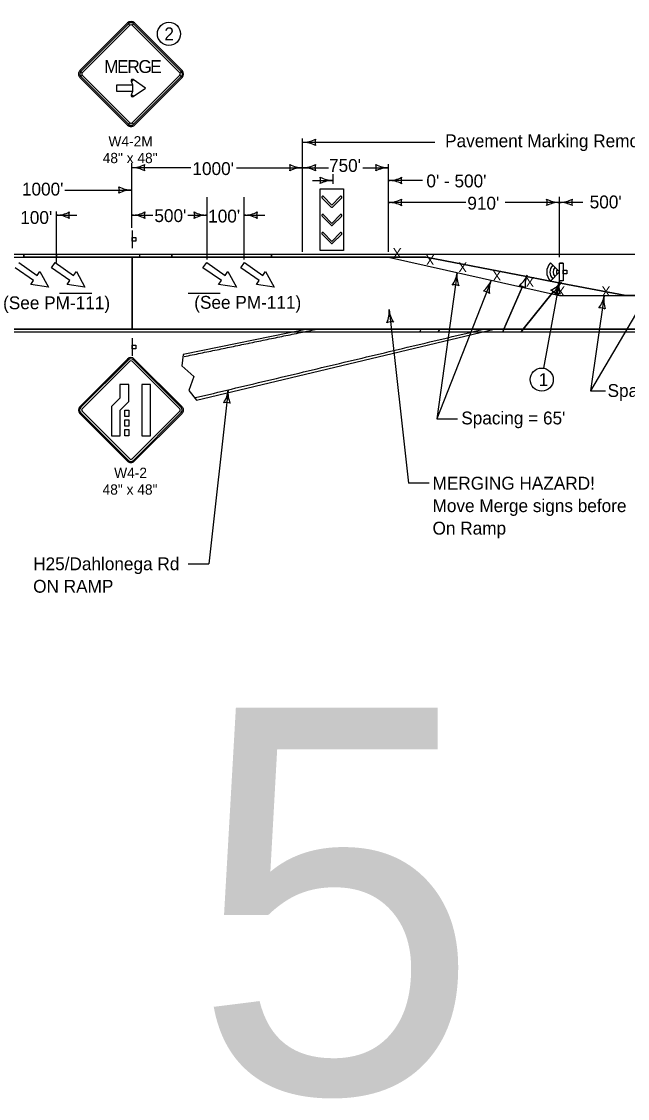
# Model space of a CAD drawing. Extents: x 10133 to 2270741, y 5363 to 1733450.
# Drawn here: x 25614 to 26557, y 10401 to 12077 of the extents above; entities that cross this region are included whole.
import ezdxf

# ---------------------------------------------------------------- set-up
doc = ezdxf.new("R2010")
doc.units = 0
for name, color, linetype in [('dsnNonPlotable', 7, 'Continuous'), ('dsnShtPlotShapeBatchPrint', 7, 'Continuous'), ('dsnStdBlockModified', 7, 'Continuous'), ('dsnStdBorder', 7, 'Continuous'), ('dsnStdNote', 7, 'Continuous'), ('Level 12', 7, 'Continuous'), ('Level 2', 7, 'Continuous'), ('SheetBorder', 7, 'Continuous'), ('SheetText', 7, 'Continuous')]:
    doc.layers.add(name, color=color, linetype=linetype)

msp = doc.modelspace()

# ---------------------------------------------------------------- linework, layer by layer
at = {"layer": 'dsnNonPlotable'}
for p, q in [((24576.8, 11710.3), (26185, 11710.3)), ((25609.6, 11702.1), (25638.2, 11682)), ((25660.4, 11693.9), (25666.1, 11702.1)), ((25666.1, 11702.1), (25694.8, 11682)), ((25896.1, 11693.9), (25901.9, 11702.1)), ((25901.9, 11702.1), (25930.5, 11682)), ((25954.9, 11693.9), (25960.6, 11702.1)), ((25960.6, 11702.1), (25989.3, 11682)), ((26185, 11710.3), (26450.8, 11650.6)), ((25632.5, 11673.8), (25603.8, 11693.9)), ((25638.2, 11682), (25642.5, 11688.1)), ((25642.5, 11688.1), (25655.8, 11663.6)), ((25689, 11673.8), (25660.4, 11693.9)), ((25694.8, 11682), (25699.1, 11688.1)), ((25699.1, 11688.1), (25712.4, 11663.6)), ((25924.8, 11673.8), (25896.1, 11693.9)), ((25930.5, 11682), (25934.8, 11688.1)), ((25934.8, 11688.1), (25948.1, 11663.6)), ((25983.6, 11673.8), (25954.9, 11693.9)), ((25989.3, 11682), (25993.6, 11688.1)), ((25993.6, 11688.1), (26006.9, 11663.6)), ((25628.2, 11667.7), (25632.5, 11673.8)), ((25684.7, 11667.7), (25689, 11673.8)), ((25920.5, 11667.7), (25924.8, 11673.8)), ((25979.3, 11667.7), (25983.6, 11673.8)), ((25655.8, 11663.6), (25628.2, 11667.7)), ((25712.4, 11663.6), (25684.7, 11667.7)), ((25948.1, 11663.6), (25920.5, 11667.7)), ((26006.9, 11663.6), (25979.3, 11667.7)), ((26450.8, 11650.6), (26599, 11650.6))]:
    msp.add_line(p, q, dxfattribs=at)
for points in [[(25673, 11654.4), (25723, 11654.4)], [(25673, 11654.4), (25723, 11654.4)], [(25873, 11654.4), (25923, 11654.4)]]:
    msp.add_lwpolyline(points, dxfattribs=at)
for points in [[(25884.3, 11491.7), (26333, 11598.3)], [(25970.2, 11577), (26073.8, 11598.3)], [(26333, 11598.3), (26597.2, 11598.3)], [(25866.6, 11555.6), (25969.4, 11576.8)]]:
    msp.add_open_spline(points, degree=1, dxfattribs=at)
at = {"layer": 'dsnShtPlotShapeBatchPrint'}
msp.add_circle((25843.2, 12058), 18, dxfattribs=at)
at = {"layer": 'dsnStdBlockModified'}
for p, q in [((26436.7, 11701.4), (26450.8, 11687.3)), ((26450.8, 11687.3), (26436.7, 11673.1)), ((26456.4, 11701), (26450.8, 11701)), ((26456.4, 11673.5), (26450.8, 11673.5))]:
    msp.add_line(p, q, dxfattribs=at)
for radius, start, end in [(20.3, 135.88, 224.0313), (15.3, 136.1665, 223.7159), (10.3, 136.7294, 223.0963), (5.32, 138.7005, 221.2995)]:
    msp.add_arc((26451.3, 11687.2), radius, start, end, dxfattribs=at)
at = {"layer": 'dsnStdBorder'}
for p, q in [((25778.9, 12075), (25704.6, 12000.7)), ((25780.2, 12073.6), (25782.4, 12071.4)), ((25786, 12071.4), (25788.2, 12073.6)), ((25863.7, 12000.7), (25789.5, 12075)), ((25704.6, 11990.1), (25778.9, 11915.9)), ((25708.2, 11997.2), (25706, 11999.4)), ((25706, 11991.4), (25708.2, 11993.6)), ((25786.2, 11985.1), (25787.3, 11986.8)), ((25789.5, 11915.9), (25863.7, 11990.1)), ((25862.4, 11999.4), (25860.2, 11997.2)), ((25860.2, 11993.6), (25862.4, 11991.4)), ((25784.3, 11984.4), (25786.2, 11985.1)), ((25786.2, 11962), (25784.3, 11962.6)), ((25787.3, 11960.3), (25786.2, 11962)), ((25782.4, 11919.4), (25780.2, 11917.2)), ((25788.2, 11917.2), (25786, 11919.4)), ((26097.8, 11788.4), (26111.9, 11802.5)), ((26097.8, 11760.1), (26111.9, 11774.2)), ((25786, 11751.8), (25786, 11724.3)), ((26097.8, 11732.1), (26111.9, 11746.2)), ((26456.4, 11701), (26456.4, 11673.5)), ((25786, 11584.3), (25786, 11556.8)), ((25778.7, 11551.8), (25704.4, 11477.6)), ((25704.5, 11477.6), (25778.7, 11551.8)), ((25778.7, 11551.8), (25778.7, 11551.8)), ((25789.3, 11551.8), (25863.6, 11477.6)), ((25863.6, 11477.6), (25789.3, 11551.8)), ((25705.8, 11476.2), (25780, 11550.5)), ((25782.2, 11548.3), (25708, 11474)), ((25782.2, 11548.3), (25782.2, 11548.3)), ((25860, 11474), (25785.8, 11548.3)), ((25788, 11550.5), (25862.2, 11476.2)), ((25780, 11394), (25705.8, 11468.3)), ((25708, 11470.5), (25782.2, 11396.2)), ((25785.8, 11396.2), (25860, 11470.5)), ((25862.2, 11468.3), (25788, 11394)), ((25704.4, 11467), (25778.7, 11392.7)), ((25778.7, 11392.7), (25704.5, 11467)), ((25863.6, 11467), (25789.3, 11392.7)), ((25789.3, 11392.7), (25863.6, 11467))]:
    msp.add_line(p, q, dxfattribs=at)
for points in [[(25780.2, 12073.6), (25706, 11999.4), (25708.2, 11997.2), (25782.4, 12071.4), (25780.2, 12073.6)], [(25862.4, 11999.4), (25788.2, 12073.6), (25786, 12071.4), (25860.2, 11997.2), (25862.4, 11999.4)], [(25706, 11991.4), (25780.2, 11917.2), (25782.4, 11919.4), (25708.2, 11993.6), (25706, 11991.4)], [(25806.5, 11973.5), (25787.3, 11986.8), (25786.2, 11985.1), (25784.3, 11984.4), (25786.3, 11978.5), (25786.3, 11968.5), (25784.3, 11962.6), (25786.2, 11962), (25787.3, 11960.3), (25806.5, 11973.5)], [(25788.2, 11917.2), (25862.4, 11991.4), (25860.2, 11993.6), (25786, 11919.4), (25788.2, 11917.2)], [(25761.9, 11968.5), (25761.9, 11978.5), (25786.3, 11978.5), (25786.3, 11968.5), (25761.9, 11968.5)], [(26114.9, 11816.5), (26114.9, 11720.5), (26078.2, 11720.5), (26078.2, 11816.5)], [(25786.1, 11735.4), (25786.1, 11741), (25791.7, 11741), (25791.7, 11735.4)], [(26450.8, 11673.5), (26450.8, 11701), (26456.4, 11701), (26456.4, 11673.5)], [(26456.4, 11684.6), (26456.4, 11690.2), (26462.1, 11690.2), (26462.1, 11684.6)], [(25786.1, 11567.9), (25786.1, 11573.5), (25791.7, 11573.5), (25791.7, 11567.9)], [(25767, 11491.1), (25753.7, 11477.9), (25753.7, 11432.3), (25767.2, 11432.3), (25767.2, 11472.3), (25780.5, 11485.5), (25780.5, 11512.3), (25767, 11512.3)], [(25800.8, 11512.3), (25800.8, 11432.3), (25814.3, 11432.3), (25814.3, 11512.3)], [(25774.5, 11472.3), (25780.5, 11472.3), (25780.5, 11462.3), (25774.5, 11462.3)], [(25774.5, 11457.3), (25780.5, 11457.3), (25780.5, 11447.3), (25774.5, 11447.3)], [(25774.5, 11442.3), (25780.5, 11442.3), (25780.5, 11432.3), (25774.5, 11432.3)]]:
    msp.add_lwpolyline(points, close=True, dxfattribs=at)
for points in [[(26081.3, 11802.5), (26081.3, 11802.4), (26095.4, 11788.3), (26095.4, 11788.3)], [(26109.5, 11804.8), (26109.5, 11804.7), (26096.6, 11791.2), (26083.7, 11804.7)], [(26081.3, 11774.2), (26081.3, 11774.2), (26095.4, 11760.1), (26095.4, 11760.1)], [(26109.5, 11776.6), (26109.5, 11776.5), (26096.6, 11762.9), (26083.7, 11776.5)], [(26081.3, 11746.2), (26081.3, 11746.1), (26095.4, 11732), (26095.4, 11732)], [(26109.5, 11748.5), (26109.5, 11748.4), (26096.6, 11734.9), (26083.7, 11748.4)], [(25780, 11550.5), (25705.8, 11476.2)], [(25782.2, 11548.3), (25708, 11474)], [(25860, 11474), (25785.8, 11548.3)], [(25862.2, 11476.2), (25788, 11550.5)], [(25705.8, 11468.3), (25780, 11394)], [(25708, 11470.5), (25782.2, 11396.2)], [(25785.8, 11396.2), (25860, 11470.5)], [(25788, 11394), (25862.2, 11468.3)]]:
    msp.add_lwpolyline(points, dxfattribs=at)
for centre, radius, start, end in [((25784.2, 12069.7), 7.5, 45, 134.9997), ((25784.2, 12069.7), 5.62, 45, 134.9997), ((25784.2, 12069.7), 2.5, 45, 134.9997), ((25710, 11995.4), 7.5, 134.9997, 225), ((25710, 11995.4), 5.62, 134.9997, 225), ((25710, 11995.4), 2.5, 134.9997, 225), ((25786.2, 11985.1), 2.03, 57.6877, 198.5814), ((25858.4, 11995.4), 2.5, 315.0002, 44.9998), ((25858.4, 11995.4), 5.62, 315.0002, 44.9998), ((25858.4, 11995.4), 7.5, 315.0002, 44.9998), ((25786.2, 11962), 2.03, 161.4183, 302.3126), ((25784.2, 11921.2), 7.5, 225, 315.0002), ((25784.2, 11921.2), 5.62, 225, 315.0002), ((25784.2, 11921.2), 2.5, 225, 315.0002), ((26082.5, 11803.6), 1.65, 42.6398, 223.799), ((26110.7, 11803.6), 1.65, 314.719, 134.9025), ((26096.6, 11789.5), 1.65, 225.3902, 315.8384), ((26082.5, 11775.4), 1.65, 42.6398, 223.799), ((26110.7, 11775.4), 1.65, 314.719, 134.9025), ((26096.6, 11761.3), 1.65, 225.3902, 315.8384), ((26082.5, 11747.3), 1.65, 42.6398, 223.799), ((26110.7, 11747.3), 1.65, 314.719, 134.9025), ((26096.6, 11733.2), 1.65, 225.3902, 315.8384), ((25784, 11546.5), 7.5, 45.0003, 135), ((25784, 11546.5), 7.5, 45.0003, 135), ((25784, 11546.5), 5.63, 45.0003, 135), ((25784, 11546.5), 5.63, 45.0003, 135), ((25784, 11546.5), 2.5, 45.0003, 135), ((25784, 11546.5), 2.5, 45.0003, 135), ((25709.8, 11472.3), 7.5, 135.0002, 224.9998), ((25709.8, 11472.3), 7.5, 135.0002, 224.9998), ((25709.8, 11472.3), 5.63, 135.0002, 224.9998), ((25709.8, 11472.3), 5.63, 135.0002, 224.9998), ((25709.8, 11472.3), 2.5, 135.0002, 224.9998), ((25709.8, 11472.3), 2.5, 135.0002, 224.9998), ((25858.2, 11472.3), 2.5, 315, 45.0003), ((25858.2, 11472.3), 2.5, 315, 45.0003), ((25858.2, 11472.3), 5.63, 315, 45.0003), ((25858.2, 11472.3), 5.63, 315, 45.0003), ((25858.2, 11472.3), 7.5, 315, 45.0003), ((25858.2, 11472.3), 7.5, 315, 45.0003), ((25784, 11398), 7.5, 224.9998, 315), ((25784, 11398), 7.5, 224.9998, 315), ((25784, 11398), 5.63, 224.9998, 315), ((25784, 11398), 5.63, 224.9998, 315), ((25784, 11398), 2.5, 224.9998, 315), ((25784, 11398), 2.5, 224.9998, 315)]:
    msp.add_arc(centre, radius, start, end, dxfattribs=at)
at = {"layer": 'dsnStdNote'}
msp.add_circle((26423.1, 11519.7), 18, dxfattribs=at)
at = {"layer": 'Level 12'}
for p, q in [((26051.2, 11718.5), (26051.2, 11895.1)), ((26257.1, 11889.1), (26051.2, 11889.1)), ((25785.4, 11756.1), (25785.4, 11856.8)), ((26185, 11718.5), (26185, 11855.2)), ((25877, 11849.6), (25785.4, 11849.6)), ((25948.2, 11849.6), (26051.2, 11849.6)), ((26051.2, 11849.6), (26091.2, 11849.6)), ((26098.5, 11824.5), (26098.5, 11839.4)), ((26145, 11849.6), (26185, 11849.6)), ((26066.5, 11829.8), (26098.5, 11829.8)), ((26237.5, 11829.7), (26185, 11829.7)), ((25681.4, 11814.9), (25785.4, 11814.9)), ((25902.5, 11706.7), (25902.5, 11803.6)), ((25960.4, 11706.7), (25960.4, 11803.6)), ((26450.8, 11710.6), (26450.8, 11804.1)), ((26305, 11795.5), (26185, 11795.5)), ((26450.8, 11795.6), (26366.2, 11795.6)), ((26487, 11795.6), (26450.8, 11795.6)), ((25668.1, 11701.9), (25668.1, 11781.3)), ((25668.1, 11775.7), (25700.1, 11775.7)), ((25786.2, 11775.7), (25818, 11775.7)), ((25872.5, 11775.7), (25902.5, 11775.7)), ((25960.4, 11775.7), (25992.4, 11775.7)), ((26291.6, 11686.1), (26260, 11458.5)), ((26344.4, 11674.1), (26260, 11458.5)), ((26450.8, 11673.5), (26425.7, 11537.5)), ((26520.4, 11650.2), (26499.2, 11502.2)), ((26586.4, 11650.2), (26499.2, 11502.2)), ((26185.7, 11628.7), (26215.8, 11358.3)), ((25935.1, 11503.3), (25905, 11232.9)), ((26499.2, 11502.2), (26522.3, 11502.2)), ((26260, 11458.5), (26292, 11458.5)), ((26247.8, 11358.3), (26215.8, 11358.3)), ((25873, 11232.9), (25905, 11232.9))]:
    msp.add_line(p, q, dxfattribs=at)
for centre, radius, start, end in [((26051.2, 11931.6), 42.5, 270, 298.0725), ((26051.2, 11846.6), 42.5, 61.9275, 90), ((26086.9, 11889.1), 16.4, 162.2666, 197.7334), ((25785.4, 11892.1), 42.5, 270, 298.0725), ((25821, 11849.6), 16.4, 162.2666, 197.7334), ((26015.5, 11849.6), 16.4, 342.2666, 17.7334), ((26051.2, 11892.1), 42.5, 241.9275, 270), ((26051.2, 11892.1), 42.5, 270, 298.0725), ((26086.8, 11849.6), 16.4, 162.2666, 197.7334), ((26149.4, 11849.5), 16.4, 342.2666, 17.7334), ((26185, 11892), 42.5, 241.9275, 270), ((25785.4, 11807.1), 42.5, 61.9275, 90), ((26051.2, 11807.1), 42.5, 90, 118.0725), ((26051.2, 11807.1), 42.5, 61.9275, 90), ((26185, 11807), 42.5, 90, 118.0725), ((25749.7, 11814.9), 16.4, 342.2666, 17.7334), ((25785.4, 11857.4), 42.5, 241.9275, 270), ((26062.8, 11829.8), 16.4, 342.2666, 17.7334), ((26098.5, 11872.3), 42.5, 241.9275, 270), ((26098.5, 11787.3), 42.5, 90, 118.0725), ((26185, 11872.2), 42.5, 270, 298.0725), ((26185, 11787.2), 42.5, 61.9275, 90), ((26220.7, 11829.7), 16.4, 162.2666, 197.7334), ((25785.4, 11772.4), 42.5, 90, 118.0725), ((26185, 11838), 42.5, 270, 298.0725), ((26185, 11753), 42.5, 61.9275, 90), ((26220.7, 11795.5), 16.4, 162.2666, 197.7334), ((26415.2, 11795.6), 16.4, 342.2666, 17.7334), ((26450.8, 11838.1), 42.5, 241.9275, 270), ((26450.8, 11753.1), 42.5, 90, 118.0725), ((26450.8, 11838.1), 42.5, 270, 298.0725), ((26450.8, 11753.1), 42.5, 61.9275, 90), ((26486.4, 11795.6), 16.4, 162.2666, 197.7334), ((25668.1, 11818.2), 42.5, 270, 298.0725), ((25668.1, 11733.2), 42.5, 61.9275, 90), ((25703.7, 11775.7), 16.4, 162.2666, 197.7334), ((25785.6, 11818.2), 42.5, 270, 298.0725), ((25785.6, 11733.2), 42.5, 61.9275, 90), ((25821.2, 11775.7), 16.4, 162.2666, 197.7334), ((25866.9, 11775.7), 16.4, 342.2666, 17.7334), ((25902.5, 11818.2), 42.5, 241.9275, 270), ((25902.5, 11733.2), 42.5, 90, 118.0725), ((25960.4, 11818.2), 42.5, 270, 298.0725), ((25960.4, 11733.2), 42.5, 61.9275, 90), ((25996, 11775.7), 16.4, 162.2666, 197.7334), ((26249.4, 11691.5), 42.5, 324.6481, 352.7206), ((26333.7, 11680.7), 42.5, 172.7206, 200.7931), ((26304.8, 11689.6), 42.5, 310.5571, 338.6296), ((26383.9, 11658.7), 42.5, 158.6296, 186.7021), ((26409.2, 11682.1), 42.5, 320.2855, 348.358), ((26492.4, 11664.9), 42.5, 168.358, 196.4305), ((26287.1, 11650.8), 16.4, 64.9872, 100.4539), ((26331.4, 11641), 16.4, 50.8963, 86.363), ((26443.6, 11638.6), 16.4, 60.6246, 96.0913), ((26478.5, 11657.1), 42.5, 322.5687, 350.6412), ((26562.3, 11643.3), 42.5, 170.6412, 198.7137), ((26143.3, 11625.1), 42.5, 336.8126, 4.8851), ((26228, 11632.3), 42.5, 184.8851, 212.9576), ((26514.6, 11615), 16.4, 62.9079, 98.3746), ((26188.7, 11593.2), 16.4, 77.1518, 112.6185), ((25892.8, 11506.9), 42.5, 327.0424, 355.1149), ((25977.5, 11499.7), 42.5, 175.1149, 203.1874), ((25932.1, 11467.8), 16.4, 67.3815, 102.8482)]:
    msp.add_arc(centre, radius, start, end, dxfattribs=at)
at = {"layer": 'Level 2'}
for p, q in [((25617.3, 11714.3), (24572.8, 11714.3)), ((25617.3, 11710.3), (25617.3, 11714.3)), ((25668.1, 11714.3), (25617.3, 11714.3)), ((25617.3, 11714.3), (25617.3, 11710.3)), ((25617.3, 11710.3), (25668.1, 11710.3)), ((25902.5, 11714.3), (25668.1, 11714.3)), ((25668.1, 11714.3), (25668.1, 11710.3)), ((25668.1, 11710.3), (25668.1, 11714.3)), ((25668.1, 11710.3), (25902.5, 11710.3)), ((25786, 11598.3), (25786, 11710.3)), ((25847.9, 11710.3), (25786, 11710.3)), ((25786, 11710.3), (25786, 11598.3)), ((25847.9, 11714.3), (25797.1, 11714.3)), ((25797.1, 11714.3), (25797.1, 11710.3)), ((25797.1, 11710.3), (25847.9, 11710.3)), ((26002.5, 11714.3), (25847.9, 11714.3)), ((25847.9, 11714.3), (25847.9, 11710.3)), ((25847.9, 11710.3), (25847.9, 11714.3)), ((26002.5, 11714.3), (25847.9, 11714.3)), ((25847.9, 11714.3), (25847.9, 11710.3)), ((25847.9, 11710.3), (26002.5, 11710.3)), ((25847.9, 11710.3), (26002.5, 11710.3)), ((26002.5, 11710.3), (25847.9, 11710.3)), ((25902.5, 11710.3), (25902.5, 11714.3)), ((26002.5, 11710.3), (26002.5, 11714.3)), ((26002.5, 11710.3), (26002.5, 11714.3)), ((26833.2, 11714.3), (26002.5, 11714.3)), ((26002.5, 11714.3), (26002.5, 11710.3)), ((26243.4, 11710.3), (26002.5, 11710.3)), ((26002.5, 11710.3), (26243.4, 11710.3)), ((26399.6, 11680.3), (26243.4, 11710.3)), ((26243.4, 11710.3), (26399.6, 11680.3)), ((26399.7, 11680.3), (26452.5, 11670.1)), ((26452.5, 11670.1), (26399.7, 11680.3)), ((26452.6, 11670.1), (26554.1, 11650.6)), ((26554.1, 11650.6), (26452.6, 11670.1)), ((26364.3, 11598.3), (26393, 11664.9)), ((26393, 11664.9), (26364.3, 11598.3)), ((26394.3, 11598.3), (26441.6, 11656.7)), ((26441.6, 11656.7), (26394.3, 11598.3)), ((26554.1, 11650.6), (26669.5, 11650.6)), ((26702.3, 11650.6), (26554.1, 11650.6)), ((26364.3, 11598.3), (24568.8, 11598.3)), ((24568.8, 11598.3), (25786, 11598.3)), ((24572.8, 11594.3), (26391.1, 11594.3)), ((24572.8, 11594.3), (26362.6, 11594.3)), ((25786, 11598.3), (26364.3, 11598.3)), ((26235.1, 11598.3), (26233.5, 11594.3)), ((26233.5, 11594.3), (26262, 11594.3)), ((26265.2, 11598.3), (26235.1, 11598.3)), ((26262, 11594.3), (26265.2, 11598.3)), ((26362.6, 11594.3), (26364.3, 11598.3)), ((26364.3, 11598.3), (26362.6, 11594.3)), ((26362.6, 11594.3), (26391.1, 11594.3)), ((26394.3, 11598.3), (26364.3, 11598.3)), ((26364.3, 11598.3), (26394.3, 11598.3)), ((26394.3, 11598.3), (26391.1, 11594.3)), ((26391.1, 11594.3), (26394.3, 11598.3)), ((26391.1, 11594.3), (26627.6, 11594.3)), ((26630.6, 11598.3), (26394.3, 11598.3))]:
    msp.add_line(p, q, dxfattribs=at)
for points in [[(25786, 11710.3), (25668.1, 11710.3), (25617.3, 11710.3)], [(26400.2, 11681.6), (26400.6, 11682.5), (26400.6, 11682.5)], [(26400.2, 11681.6), (26400.2, 11681.6)], [(26452.6, 11670.1), (26452.5, 11670.1)], [(26453.3, 11671.1), (26453.7, 11671.6), (26453.7, 11671.6)], [(26394.3, 11598.3), (26603.1, 11598.3), (26698.2, 11598.3)]]:
    msp.add_lwpolyline(points, dxfattribs=at)
for centre, radius, start, end in [((26361.4, 11698.9), 42.5, 309.2655, 336.072), ((26361.4, 11698.9), 42.5, 309.2655, 334.0959), ((26439.8, 11666.1), 42.5, 160.5422, 185.4105), ((26439.8, 11666.1), 42.5, 160.5422, 185.4105), ((26361.4, 11698.9), 42.5, 334.0959, 336.072), ((26439.8, 11666.1), 42.5, 157.3556, 160.5422), ((26439.8, 11666.1), 42.5, 158.6034, 160.5422), ((26361.4, 11698.9), 42.5, 337.3204, 337.338), ((26420.5, 11698.1), 42.5, 293.3393, 318.8219), ((26420.5, 11698.1), 42.5, 293.3393, 318.8219), ((26486.9, 11645.1), 42.5, 143.9415, 169.4842), ((26486.9, 11645.1), 42.5, 143.9415, 169.4842), ((26420.5, 11698.1), 42.5, 318.8219, 320.5615), ((26486.9, 11645.1), 42.5, 141.4294, 143.9415), ((26420.5, 11698.1), 42.5, 321.3942, 321.4118), ((26386.9, 11649.6), 16.4, 68.0792, 85.0713), ((26386.9, 11649.6), 16.4, 49.6046, 85.0713), ((26386.9, 11649.6), 16.4, 49.6046, 68.0792), ((26431.5, 11643.8), 16.4, 51.9095, 69.1451), ((26431.5, 11643.8), 16.4, 33.6784, 69.1451), ((26431.5, 11643.8), 16.4, 33.6784, 51.9095)]:
    msp.add_arc(centre, radius, start, end, dxfattribs=at)
at = {"layer": 'SheetBorder'}
for p, q in [((26058.5, 11598.3), (25865.3, 11558.9)), ((25886, 11487.7), (26349.4, 11598.3)), ((26349.4, 11598.3), (26058.5, 11598.3))]:
    msp.add_line(p, q, dxfattribs=at)
msp.add_lwpolyline([(25865.3, 11558.9), (25863.2, 11541.1), (25881.9, 11524.5), (25874.2, 11502.9), (25886, 11487.7)], dxfattribs=at)

# ---------------------------------------------------------------- texts
at = {"layer": 'dsnShtPlotShapeBatchPrint'}
msp.add_text('2', height=20, dxfattribs=at).set_placement((25836.1, 12048))
at = {"layer": 'dsnStdBorder'}
for s, height, p in [('M', 20, (25742.3, 11997.1)), ('E', 20, (25762.5, 11997.1)), ('R', 20, (25778.5, 11997.1)), ('G', 20, (25795.7, 11997.1)), ('E', 20, (25813.9, 11997.1)), ('W4-2M', 16, (25749, 11882.7)), ('48" x 48"', 16, (25740.1, 11856.7)), ('(See PM-111)', 20, (25585.1, 11629.3)), ('(See PM-111)', 20, (25882.5, 11630)), ('W4-2', 16, (25757.9, 11366.6)), ('48" x 48"', 16, (25739.9, 11340.6))]:
    msp.add_text(s, height=height, dxfattribs=at).set_placement(p)
for p in [(26205, 11724.4), (26256.3, 11713.6), (26306.9, 11702.5), (26360.3, 11689.2), (26411.5, 11679.3), (26459.3, 11665), (26529.9, 11665)]:
    msp.add_text('X', height=15, rotation=180, dxfattribs=at).set_placement(p)
at = {"layer": 'dsnStdNote'}
msp.add_text('1', height=20, dxfattribs=at).set_placement((26418.4, 11509.7))
at = {"layer": 'Level 12'}
for s, p in [('Pavement Marking Removal Limits', (26272.9, 11881.5)), ("1000'", (25879.7, 11838.2)), ("750'", (26092.2, 11843.1)), ("0' - 500'", (26243.7, 11819)), ("1000'", (25614.4, 11806.3)), ("910'", (26307.4, 11784.4)), ("500'", (26497.8, 11786.3)), ("100'", (25611.8, 11762.1)), ("500'", (25820.5, 11765)), ("100'", (25904.2, 11764.3)), ("Spacing = 65'", (26525.6, 11492.7)), ("Spacing = 65'", (26298, 11450)), ('MERGING HAZARD!', (26253.3, 11348.5)), ('Move Merge signs before', (26253.3, 11313.5)), ('On Ramp', (26253.3, 11278.5)), ('H25/Dahlonega Rd', (25631.9, 11223)), ('ON RAMP', (25631.9, 11188))]:
    msp.add_text(s, height=20, dxfattribs=at).set_placement(p)
at = {"layer": 'SheetText'}
msp.add_text('5', height=600, dxfattribs=at).set_placement((25880.7, 10409.2))

doc.saveas('drawing.dxf')
